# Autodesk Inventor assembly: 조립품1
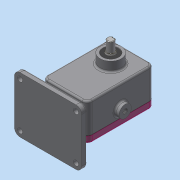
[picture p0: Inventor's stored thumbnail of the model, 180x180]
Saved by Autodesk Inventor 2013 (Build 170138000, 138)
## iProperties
Created: 2020-04
Part Number: 조립품1
Document SubType Name: Assembly
Designer: dgall
Author: dgall
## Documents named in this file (11)
- C:\Users\dgall\Desktop\700407V1011\조립품1.iam
- C:\Users\dgall\Desktop\700407V1011\본체.ipt
- C:\Users\dgall\Desktop\700407V1011\메인축.ipt
- C:\Users\dgall\Desktop\700407V1011\서브축.ipt
- C:\Users\dgall\Desktop\700407V1011\키 6 x 6 x 18.ipt
- C:\Users\dgall\Desktop\700407V1011\베어링부시.ipt
- C:\Users\dgall\Desktop\700407V1011\스퍼기어.ipt
- C:\Users\dgall\Desktop\700407V1011\오일 실 16 28 7.ipt
- C:\Users\dgall\Desktop\700407V1011\커버.ipt
- C:\Users\dgall\Desktop\700407V1011\볼트 M5.ipt
- C:\Users\dgall\Desktop\700407V1011\개스킷.ipt
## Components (1 placed, 1 different names)
1. 개스킷:1
